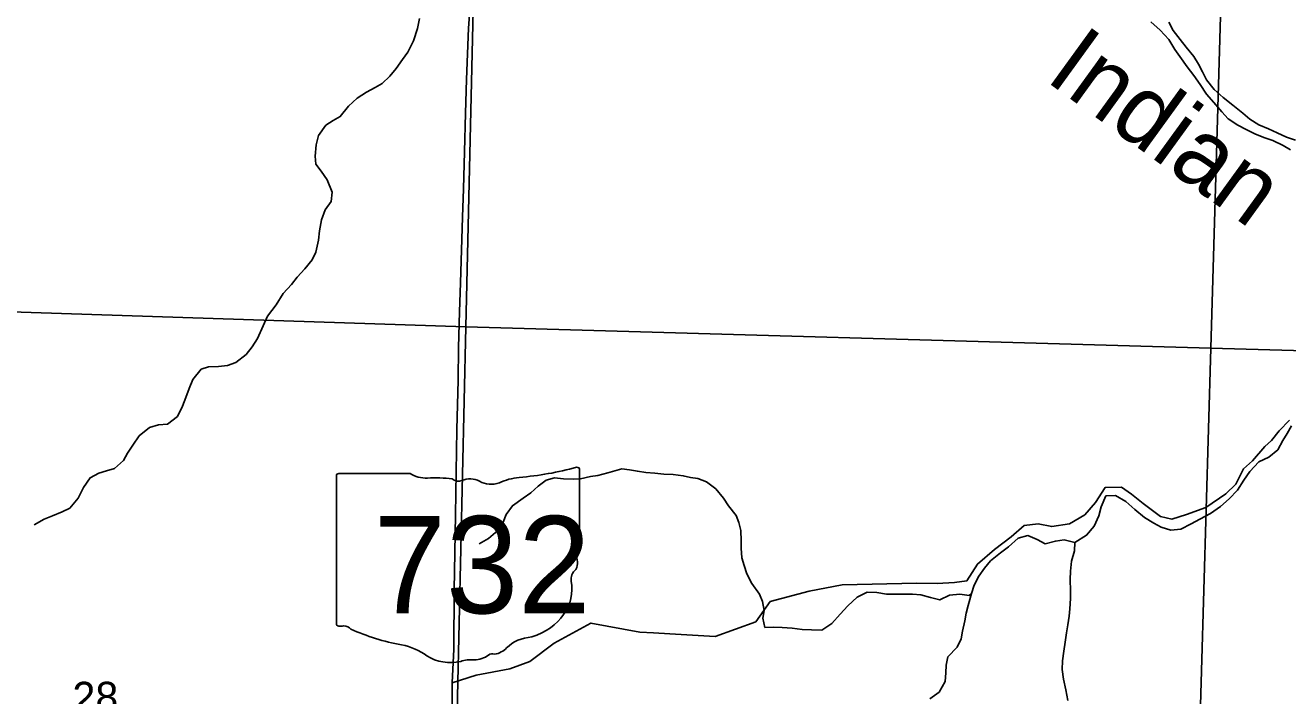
# Model space of a CAD drawing. Extents: x 1310247 to 1552180, y 377264 to 706493.
# Drawn here: x 1326623 to 1335657, y 522581 to 527377 of the extents above; entities that cross this region are included whole.
import ezdxf

# ---------------------------------------------------------------- set-up
doc = ezdxf.new("R2010")
doc.units = 0
for name, color, linetype in [('GM_X_Major_River', 7, 'Continuous'), ('GM_X_Major_River_Text', 7, 'Continuous'), ('GM_X_Minor_River', 7, 'Continuous'), ('GM_X_Section', 7, 'Continuous'), ('GM_X_Section_Text', 7, 'Continuous'), ('GM_X_State_Location', 7, 'Continuous'), ('GM_X_State_Route', 7, 'Continuous'), ('GM_X_State_Shield', 7, 'Continuous'), ('GM_X_Township_ROW', 7, 'Continuous')]:
    doc.layers.add(name, color=color, linetype=linetype)

msp = doc.modelspace()

# ---------------------------------------------------------------- linework, layer by layer
at = {"layer": 'GM_X_Major_River'}
for points in [[(1334678.2, 527400.4), (1334745.2, 527340.9), (1334806, 527275.4), (1334848.7, 527204.3), (1334885.7, 527153.4), (1334938.4, 527080), (1334985.2, 527016.9), (1335030, 526953.8), (1335076.7, 526884.6), (1335127.6, 526823.3), (1335186.4, 526757.9), (1335231.5, 526706.8), (1335298.8, 526661.3), (1335360.3, 526629.9), (1335425.9, 526598.5), (1335493.5, 526571), (1335549.3, 526551.8), (1335624.8, 526516.2), (1335676.3, 526485)], [(1335711.9, 526554.5), (1335648.1, 526575.9), (1335580.6, 526607.4), (1335518.9, 526634.7), (1335449.3, 526664.2), (1335386, 526705.7), (1335334.7, 526746.8), (1335263.7, 526804.5), (1335194.6, 526860.1), (1335129.6, 526917.6), (1335074.8, 526986.9), (1335045.9, 527043.7), (1335019, 527098.5), (1334984, 527153.4), (1334929.3, 527220.7), (1334886.2, 527273.8), (1334837.4, 527339), (1334806.5, 527397.8)]]:
    msp.add_lwpolyline(points, dxfattribs=at)
at = {"layer": 'GM_X_Minor_River'}
for points in [[(1329444.1, 527425.5), (1329430.3, 527353.6), (1329401.9, 527266), (1329359.8, 527184.7), (1329322.3, 527131.4), (1329276.6, 527068.3), (1329231.1, 527013.2), (1329177.6, 526960.4), (1329126.7, 526931.5), (1329065.7, 526896.9), (1328998.4, 526854.4), (1328934.8, 526797.8), (1328876.8, 526722.9), (1328825.9, 526694.1), (1328772.9, 526661.3), (1328720.9, 526588.3), (1328703.2, 526520.5), (1328697.1, 526440.3), (1328701.7, 526384), (1328740.5, 526332.9), (1328783.1, 526271.6), (1328818.9, 526182.4), (1328811.2, 526116.4), (1328769.5, 526057.2), (1328741.7, 525985.7), (1328727.6, 525905.7), (1328719.9, 525839.7), (1328701.6, 525753.8), (1328676.2, 525698.3), (1328624.4, 525635.3), (1328568.7, 525574.5), (1328527.3, 525523.3), (1328467.5, 525458.6), (1328419.3, 525377.5), (1328355.1, 525296.8), (1328325.2, 525227.3), (1328284.8, 525136), (1328247.2, 525076.7), (1328203.7, 525021.6), (1328130.1, 524965.2), (1328069.3, 524942.6), (1328005, 524936.2), (1327932.7, 524933.9), (1327882.2, 524917.1), (1327822.1, 524842.4), (1327796.4, 524778.8), (1327772.7, 524713.2), (1327747.1, 524651.6), (1327713.1, 524578.2), (1327641.5, 524523.7), (1327575.2, 524517.3), (1327510.5, 524498.9), (1327436.8, 524438.5), (1327393, 524373.3), (1327353.5, 524316.1), (1327326, 524262.6), (1327262.4, 524206), (1327203.8, 524189.4), (1327149.3, 524172.7), (1327086.3, 524140.1), (1327038.4, 524071.1), (1327000.3, 523993.8), (1326940.4, 523923), (1326887.5, 523896.2), (1326818.6, 523867.8), (1326757.9, 523843.2), (1326686.6, 523802.8)], [(1335685.1, 524510.5), (1335651.9, 524457), (1335622.7, 524405.5), (1335587.2, 524340), (1335521.9, 524287.2), (1335450.9, 524252.5), (1335385.3, 524183.6), (1335341.9, 524122.3), (1335298.2, 524051), (1335238.7, 523988), (1335175.4, 523935.1), (1335104.1, 523884.4), (1335029, 523843.9), (1334966.1, 523809), (1334891.1, 523772.5), (1334820.7, 523765.9), (1334750.9, 523785.4), (1334699.4, 523814.5), (1334632, 523856), (1334563, 523913.6), (1334498, 523969.1), (1334424.6, 524012.7), (1334356.4, 524010.1), (1334322.6, 523932.6), (1334305.2, 523866.7), (1334271.6, 523793.2), (1334218, 523728.1), (1334132.7, 523677.7), (1334056.8, 523695.3), (1333994.4, 523686.5), (1333921.8, 523667.9), (1333864.3, 523699.2), (1333796.7, 523726.7), (1333728, 523708), (1333658.5, 523645.3), (1333601.4, 523602.3), (1333530, 523545.6), (1333486.8, 523492.3), (1333445.4, 523435), (1333414, 523371.4), (1333394.7, 523311.6), (1333370.8, 523225.9), (1333355.6, 523170), (1333346.4, 523116), (1333330.8, 523042.1), (1333319.7, 522988.2), (1333290.3, 522928.6), (1333224.6, 522857.8), (1333213.4, 522799.8), (1333210.2, 522743.7), (1333204.9, 522681.6), (1333163.1, 522606.3), (1333095.9, 522557.5)], [(1332971.2, 523306.3), (1332785.6, 523307.1), (1332715.7, 523318.9), (1332647.6, 523320.6), (1332576.6, 523286.2), (1332508.8, 523223.7), (1332453.1, 523164.8), (1332395.3, 523098), (1332321.9, 523049.7), (1332249.7, 523051.5), (1332181.6, 523055.2), (1332111.7, 523062.9), (1332039.6, 523068.7), (1331977.5, 523070.2), (1331915.3, 523069.8), (1331900.9, 523134.3), (1331910.4, 523190.3), (1331898, 523254.8), (1331877.3, 523307.5), (1331823.1, 523383.1), (1331786.8, 523452.2), (1331766.3, 523512.9), (1331751.6, 523567.4), (1331745.4, 523635.8), (1331746.7, 523687.9), (1331742.6, 523762.3), (1331730, 523818.8), (1331709.2, 523869.5), (1331654.9, 523939), (1331618.2, 523994.1), (1331563.7, 524059.7), (1331496.9, 524111.5), (1331435.3, 524135.1), (1331383.4, 524142.4), (1331331.5, 524153.7), (1331259.6, 524163.5), (1331191.5, 524165.2), (1331127.5, 524172.8), (1331063.4, 524176.4), (1331003.5, 524185.9), (1330945.7, 524197.3), (1330891.7, 524202.7), (1330841.2, 524189.9), (1330790.7, 524175.1), (1330720.1, 524156.8), (1330667.7, 524148), (1330595.1, 524131.7), (1330542.9, 524129), (1330474.8, 524132.7), (1330408.8, 524140.3), (1330350.3, 524123.7), (1330293, 524079), (1330241.6, 524032.1), (1330186.5, 523993.3), (1330108.9, 523939), (1330063.2, 523876), (1330041.8, 523822.3), (1330004.2, 523763), (1329936.5, 523704.5), (1329871.4, 523668)], [(1334132.7, 523677.7), (1334131.4, 523617.5), (1334109.8, 523543.7), (1334102.3, 523471.7), (1334101, 523411.5), (1334101.3, 523331.3), (1334102.2, 523277.1), (1334098.6, 523202.9), (1334093.5, 523148.9), (1334084.2, 523086.9), (1334075, 523030.9), (1334063.5, 522962.9), (1334054.1, 522898.9), (1334044.7, 522830.9), (1334043.4, 522768.8), (1334051.9, 522698.4), (1334068.4, 522621.8), (1334082.8, 522545.3)], [(1333394.7, 523311.6), (1333376.3, 523298), (1333310.3, 523307.4), (1333235.9, 523298.9), (1333167, 523266.2), (1333101.1, 523283.6), (1333031.3, 523303), (1332971.2, 523306.3)]]:
    msp.add_lwpolyline(points, dxfattribs=at)
at = {"layer": 'GM_X_Section'}
for points in [[(1324860.1, 530690.5), (1329900.3, 530577.3), (1329774.9, 525219.4), (1324638.2, 525389)], [(1329900.3, 530577.3), (1335265.1, 530472), (1335106, 525066.9), (1329774.9, 525219.4)], [(1335265.1, 530472), (1340935.4, 530282.5), (1340857.1, 524905.5), (1335106, 525066.9)], [(1329774.9, 525219.4), (1329657.3, 519925.3), (1324430.7, 520023.1), (1324638.2, 525389)], [(1329774.9, 525219.4), (1335106, 525066.9), (1334956.2, 519873.7), (1329657.3, 519925.3)], [(1335106, 525066.9), (1340857.1, 524905.5), (1340514, 519745), (1334956.2, 519873.7)]]:
    msp.add_lwpolyline(points, close=True, dxfattribs=at)
at = {"layer": 'GM_X_State_Route'}
msp.add_lwpolyline([(1329676.9, 522494.9), (1329678.1, 522673.6), (1329688.5, 522913.6), (1329691.1, 523336.7), (1329701.2, 523874.8), (1329709.9, 524484.2), (1329719.7, 524838.8), (1329723.3, 525072.6), (1329729.5, 525326), (1329737.7, 525534.1), (1329751, 526003.7), (1329758.8, 526206.2), (1329766.5, 526470.9), (1329774.2, 526746.8), (1329779.8, 526988.3), (1329795.2, 527356.3), (1329803, 527487.8)], dxfattribs=at)
at = {"layer": 'GM_X_State_Shield'}
for p, q in [((1330589.6, 523644.1), (1330589.6, 524196.8)), ((1328849.4, 524152.5), (1328849.4, 523095.8)), ((1329376.1, 524170.7), (1328866.5, 524170.7)), ((1330589.4, 523644.2), (1330589.6, 523644.1))]:
    msp.add_line(p, q, dxfattribs=at)
for centre, major_axis, start_param, end_param in [((1329969.7, 525611.2), (1845.5, 0), 4.814394, 5.042369), ((1330570.3, 524199.1), (19.4, 0), 6.141152, 7.989035), ((1328869.3, 524154.7), (20.2, 0), 1.712693, 3.28349), ((1329497.5, 524293.3), (195.5, 0), 4.042523, 4.731795), ((1329562.4, 523577.4), (702, 0), 1.404758, 1.657858), ((1329721.7, 524160.2), (56.4, 0), 3.836095, 5.185415), ((1329804.5, 524038.1), (117.3, 0), 0.950623, 2.079405), ((1329955.9, 524205.6), (141.1, 0), 4.081561, 5.145723), ((1330205.1, 523847.9), (371.3, 0), 1.699011, 2.107814), ((1330585.1, 523603.5), (30, 0), 1.883978, 3.671073), ((1330394.4, 523533.7), (180, 0), 5.934695, 6.695948), ((1330568.9, 523642), (20.7, 0), 5.05454, 6.418171), ((1330659, 523412.8), (130.9, 0), 2.387724, 3.262537), ((1330073.1, 523342.5), (461.6, 0), 5.101752, 6.440018), ((1328869.5, 523093.5), (20.3, 0), 3.00124, 4.508301), ((1328872.6, 523201.6), (155.2, 0), 4.665946, 4.897461), ((1328904.3, 523034.9), (56, 0), 0.519207, 1.627899), ((1329610.9, 523984.2), (1332.7, 0), 4.195997, 4.488961), ((1329213.6, 522621.1), (417, 0), 0.823519, 1.323587), ((1330267.7, 522799.2), (252.8, 0), 1.647645, 2.488434), ((1329664.6, 523029.6), (264.6, 0), 4.026481, 4.996735), ((1329817.5, 522664.3), (217.4, 0), 1.495662, 1.94098), ((1329836.8, 522950.5), (141, 0), 4.691044, 5.507374), ((1329964.3, 522848.2), (39.7, 0), 1.147584, 2.315152), ((1329947.4, 522993.4), (149.1, 0), 4.937069, 5.64225)]:
    msp.add_ellipse(centre, major_axis=major_axis, ratio=0.8, start_param=start_param, end_param=end_param, dxfattribs=at)
at = {"layer": 'GM_X_Township_ROW'}
msp.add_lwpolyline([(1335669.9, 524550.9), (1335596.8, 524475.2), (1335540, 524407), (1335494.2, 524364.5), (1335406, 524261.3), (1335341.6, 524203.4), (1335285.4, 524095), (1335214.5, 524025.3), (1335070.1, 523926.2), (1334931.7, 523877), (1334828, 523844.7), (1334746.4, 523863.8), (1334621.3, 523956.8), (1334539.3, 524022), (1334466.9, 524072.9), (1334350.3, 524069.2), (1334282, 523963.3), (1334204.4, 523873.7), (1334095.5, 523809.4), (1333968.2, 523790), (1333870.5, 523809.7), (1333771.6, 523797.2), (1333678.2, 523716.3), (1333558.3, 523626.3), (1333437.9, 523522.3), (1333361.2, 523402.6), (1333272.3, 523389.9), (1333147.5, 523382.4), (1333003, 523385.7), (1332468.1, 523373.3), (1332233.5, 523329.7), (1331953.4, 523253.7), (1331849.6, 523108.9), (1331560.5, 523005.1), (1331235.7, 523023.1), (1331119.5, 523031.4), (1331021.2, 523035), (1330670.1, 523100.1), (1330407.6, 522957.2), (1330234, 522825), (1330089.3, 522772.1), (1329848.6, 522726.7), (1329678.1, 522673.6)], dxfattribs=at)

# ---------------------------------------------------------------- texts
at = {"layer": 'GM_X_Major_River_Text'}
msp.add_text('Indian', height=500.04, rotation=324.05783, dxfattribs=at).set_placement((1333911.9, 526986.6))
at = {"layer": 'GM_X_Section_Text'}
msp.add_text('28', height=221, rotation=0.00001, dxfattribs=at).set_placement((1326959.9, 522459.2))
at = {"layer": 'GM_X_State_Location'}
msp.add_text('732', height=1, rotation=0.00001, dxfattribs=at).set_placement((1329346.9, 523481.2))
for s in ['s', 'r']:
    msp.add_text(s, height=1, dxfattribs=at).set_placement((1329699.9, 523553.9))
at = {"layer": 'GM_X_State_Shield'}
msp.add_text('732', height=696.1, dxfattribs=at).set_placement((1329115.1, 523170.3))

doc.saveas('drawing.dxf')
